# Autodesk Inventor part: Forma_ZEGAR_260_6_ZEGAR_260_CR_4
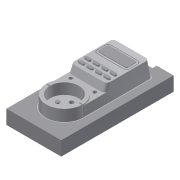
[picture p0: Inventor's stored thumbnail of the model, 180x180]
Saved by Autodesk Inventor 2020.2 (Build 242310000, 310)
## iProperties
Created: 2015-01
Part Number: Forma_ZEGAR_260_6_ZEGAR_260_CR_4
Material: Ogólny
Document SubType Name: Modeling
Designer: F.Stasiak
Density: 1 g/cm^3
Appearance: Domyślna
Catalog Web Link: www.expertbooks.pl
Manager: www.cadconsulting.pl
Company: Fabian Stasiak CAD Consulting
Author: F.Stasiak
Subject: Zbiór ćwiczeń. Autodesk Inventor 2020. Kurs Professional
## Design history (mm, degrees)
node "Forma_ZEGAR_260_4_ZEGAR_260_CR_Base"
feature "Bryła1::Forma_ZEGAR_260_4_ZEGAR_260_CR_Base"
tag "Bryła wyprowadzona1"
node "Bryła1"
feature "Forma_ZEGAR_260_4_ZEGAR_260_CR_Base_Bodies"
